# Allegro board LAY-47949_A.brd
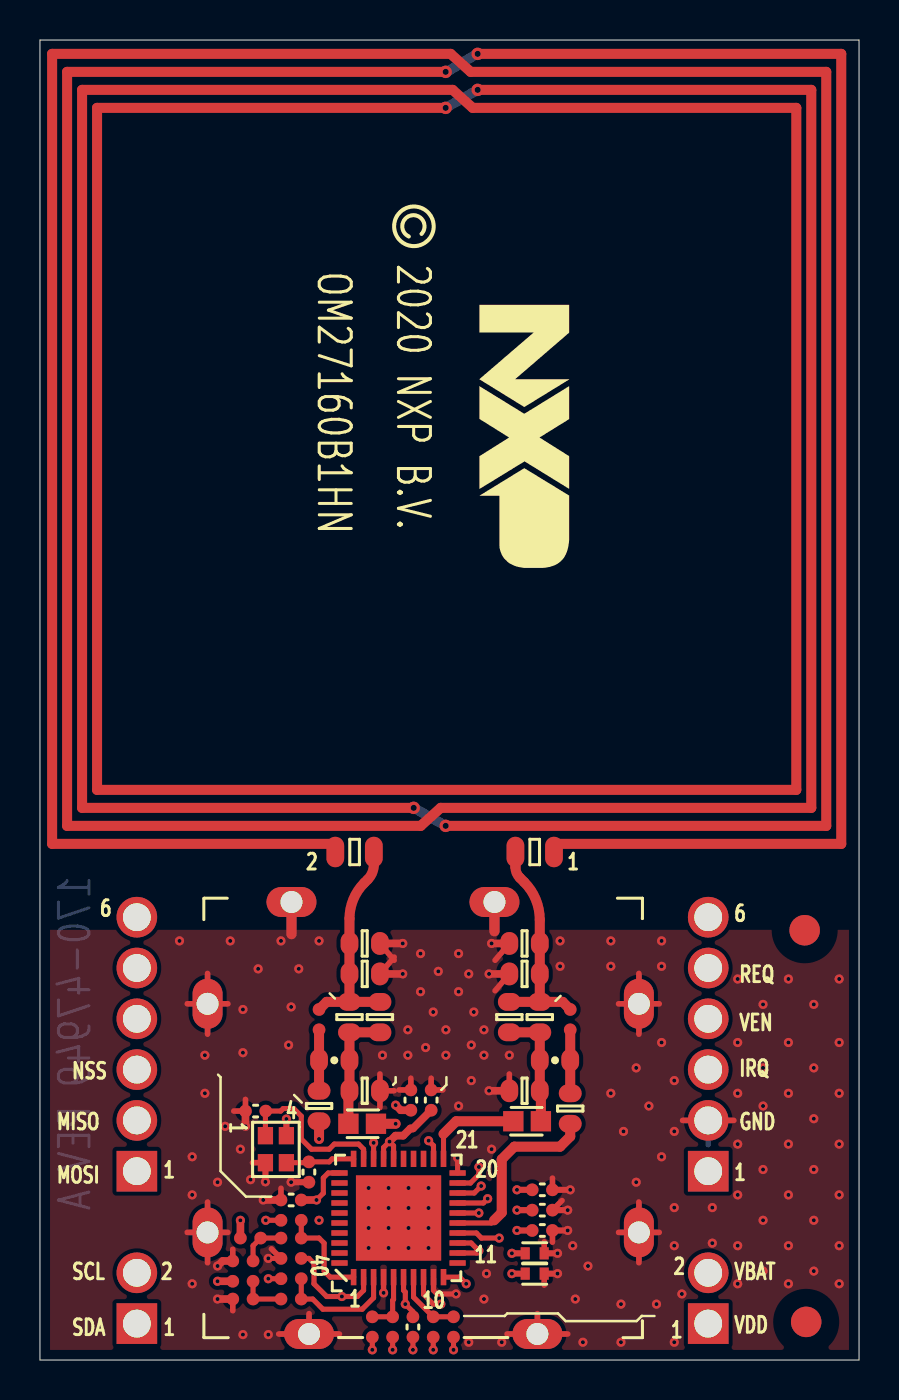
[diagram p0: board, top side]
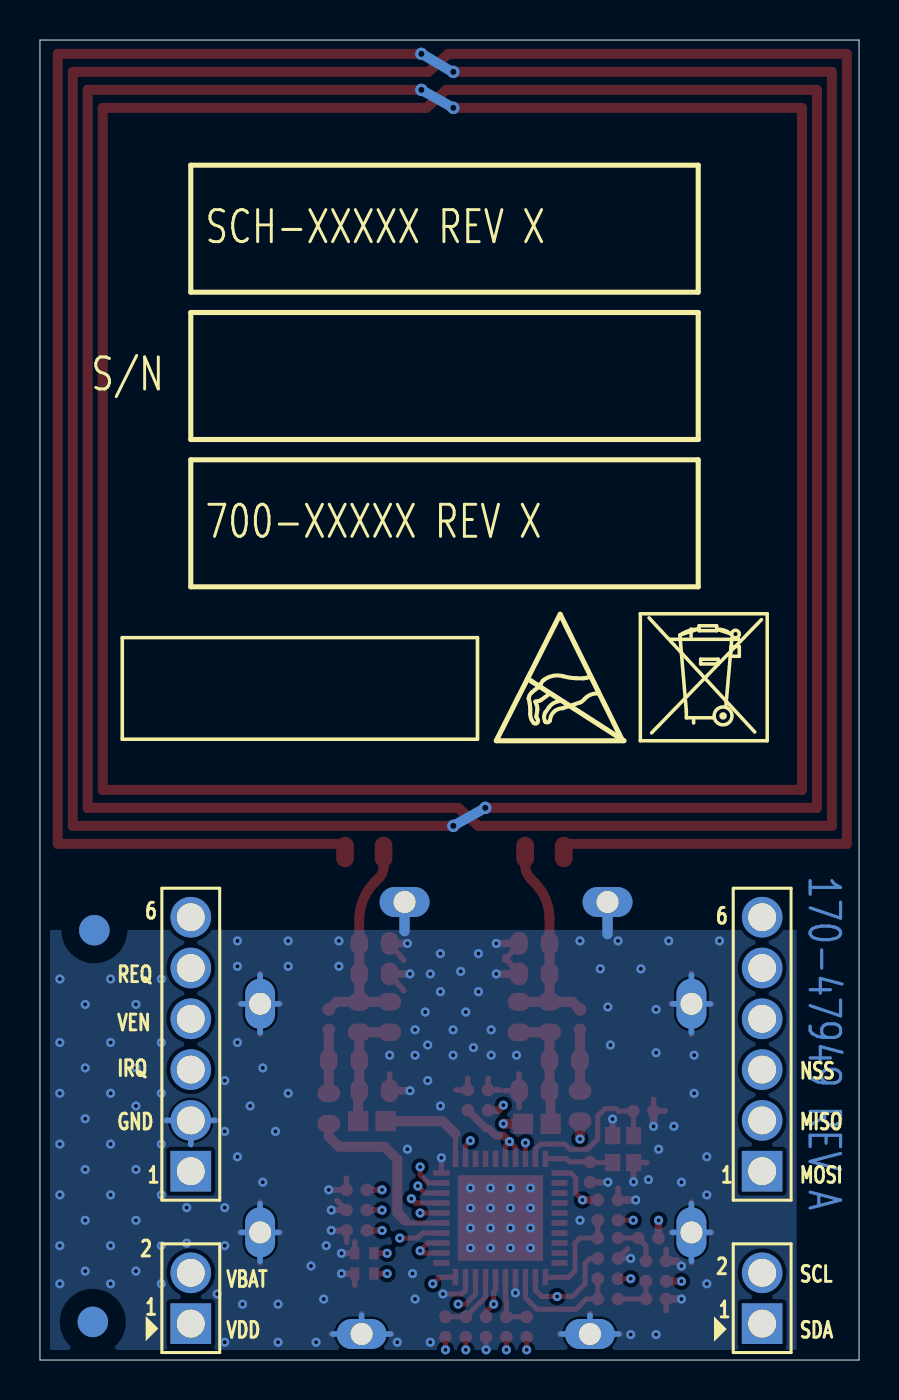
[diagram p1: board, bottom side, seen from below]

Outline 41 x 66 mm; copper layers: TOP, L2_INT_1, L3_INT_2, BOTTOM. Coordinates in mm from the lower left corner of the outline.
Outline path: 0,66 0,0 41,0 41,66 0,66

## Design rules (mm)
constraint set DEFAULT: min track width 0.127

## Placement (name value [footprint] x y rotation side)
ANT1  ANTENNA  [ANTENNA_4T_40X40]  25.76 25.81 270 top
C1  10PF  [CC0402_25]  10.79 12.45 180 top
C2  10PF  [CC0402_25]  13.46 9.4 270 top
C3  2.2UF  [CC0402_25]  25.15 7.49 180 top
C4  2.2UF  [CC0402_25]  25.15 6.48 180 top
C6  0.1uF  [CC0402_25]  25.15 8.51 0 top
C7  2.2UF  [CC0402_25]  19.58 13 270 top
C8  2.2UF  [CC0402_25]  12.57 8 0 top
C9  1uF  [CC0402_25]  18.67 1.65 270 top
C10  4.7uF  [CC0402_TOL0P15]  24.77 4.32 0 top
C11  4.7uF  [CC0402_TOL0P15]  24.77 5.33 0 top
C12  0.1uF  [CC0402_25]  18.57 13 90 top
C13  1000pF  [CC0603_OV]  26.54 12.57 90 top
C14  56 PF  [CC0603_OV]  23.49 17.14 90 top
C15  22 PF  [CC0603_OV]  25.02 17.14 90 top
C16  680PF  [CC0603_OV]  24.26 13.46 180 top
C17  120PF  [CC0603_OV]  24.26 20.83 180 top
C18  2.2PF  [CC0603_OV]  24.26 19.3 180 top
C19  680PF  [CC0603_OV]  16.26 13.46 180 top
C20  120PF  [CC0603_OV]  16.26 20.83 180 top
C21  2.2PF  [CC0603_OV]  16.26 19.3 180 top
C22  22 PF  [CC0603_OV]  15.49 17.14 90 top
C23  56 PF  [CC0603_OV]  17.02 17.14 90 top
C24  1000pF  [CC0603_OV]  13.97 12.7 90 top
J1  HDR_1X2  [SKT1X2_2P54_TH_BSE]  33.45 1.82 90 bottom
J2  HDR_1X2  [SKT1X2_2P54_TH_BSE]  4.85 1.82 90 bottom
J3  AGPS1-06-BCZ-1.3  [SKT1X6_2P54_TH_BSE]  33.45 9.44 90 bottom
J4  AGPS1-06-BCZ-1.3  [SKT1X6_2P54_TH_BSE]  4.85 9.44 90 bottom
L1  160nH  [IND_0603A]  24.38 11.94 0 top
L2  160nH  [IND_0603A]  16.13 11.81 180 top
NOREF  -  []  33.45 9.44 90 top
NOREF#2  -  []  25.34 3.99 90 top
NOREF#3  -  []  34.72 -4.53 0 top
NOREF#4  -  []  29.64 -7.07 0 top
NOREF#5  -  []  18.69 56.68 270 top
NOREF#6  -  []  24.19 3.99 0 top
NOREF#7  -  []  4.85 9.44 90 top
NOREF#8  -  []  -379.73 257.05 0 top
NOREF#9  -  []  34.72 -4.53 90 top
NOREF#10  -  []  25.34 5.01 90 top
NOREF#11  -  []  6.12 -4.53 90 top
NOREF#12  -  []  24.29 5.33 0 top
NOREF#13  -  []  -406.4 -264.03 0 top
NOREF#14  -  []  29.98 6.38 90 top
NOREF#15  -  []  -21.59 -39.88 0 top
NOREF#16  -  []  13.47 1.3 0 top
NOREF#17  -  []  33.45 1.82 90 top
NOREF#18  -  []  6.12 -4.53 0 top
NOREF#19  -  [unnamed#2]  38.28 21.49 0 top
NOREF#20  -  []  3.58 -7.07 90 top
NOREF#21  -  []  22 52.75 270 top
NOREF#22  -  []  1.04 -7.07 0 top
NOREF#23  -  []  0 66 0 top
NOREF#24  -  []  8.39 1.3 0 top
NOREF#25  -  []  32.18 -7.07 90 top
NOREF#26  -  []  19.1 31.04 0 top
NOREF#27  -  []  4.85 1.82 90 top
NOREF#28  -  [unnamed#2]  38.35 1.91 0 top
NOREF#29  -  []  24.29 4.32 0 top
NOREF#30  -  []  4.85 4.36 0 top
NOREF#31  -  []  14.86 25.81 0 top
NOREF#32  -  []  29.98 1.3 90 top
NOREF#33  -  []  33.45 9.44 90 top
NOREF#34  -  []  41 0 90 top
NOREF#35  -  []  4.85 9.44 90 top
NOREF#36  -  []  24.19 5.01 0 top
NOREF#37  -  []  175.18 226.56 0 top
NOREF#38  -  []  12.59 22.9 0 top
NOREF#39  -  []  18.14 30.96 180 bottom
NOREF#40  -  []  33.45 46.02 180 bottom
NOREF#41  -  []  36.88 31.04 180 bottom
NOREF#42  -  []  10.95 30.96 180 bottom
NOREF#43  -  [unnamed#2]  38.35 1.91 180 bottom
NOREF#44  -  []  33.45 38.66 180 bottom
NOREF#45  -  []  33.45 53.39 180 bottom
NOREF#46  -  [unnamed#2]  38.28 21.49 180 bottom
R1  0  [RC0402_25]  12.57 6.1 0 top
R2  0  [RC0402_25]  12.57 3.05 0 top
R3  0  [RC0402_25]  17.65 1.65 90 top
R4  0  [RC0402_25]  20.7 1.65 90 top
R5  0  [RC0402_25]  19.69 1.65 90 top
R6  0  [RC0402_25]  16.64 1.65 90 top
R7  0  [RC0402_25]  12.57 4.06 0 top
R8  0  [RC0402_25]  12.57 6.99 0 top
R9  100k  [RC0402_25]  12.57 5.08 180 top
R10  100k  [RC0402_25]  10.54 6.1 0 top
R11  100k  [RC0402_25]  10.16 3.94 0 top
R12  100k  [RC0402_25]  10.16 4.95 180 top
R13  100k  [RC0402_25]  10.16 3.05 180 top
R14  0  [RC0402_25]  26.54 17.02 90 top
R15  2.2K  [RC0603_OV]  25.78 14.99 180 top
R16  1.5 OHM  [RC0805_OV]  24.77 25.4 0 top
R17  1.5 OHM  [RC0805_OV]  15.75 25.4 180 top
R18  2.2K  [RC0603_OV]  14.73 14.99 180 top
R19  0  [RC0402_25]  13.97 17.02 90 top
SH1  RF-SHIELD-8  [SHIELD_PN7150_22X22]  19.19 12.1 0 top
U1  PN7160B1HN/C100  [QFN40_0P5_4P25X4P25]  17.95 7.1 90 top
Y1  27.12MHz  [XTAL4_2P1X1P7MM_SM]  11.81 10.54 270 top

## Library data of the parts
ANT1 = L104
C1-C4 C6-C24 = CAP_NP
J1 J2 = CONN_HDR_2X1
J3 J4 = CONN_HDR_6X1
L1 L2 = INDUCTOR
R1-R19 = RES
SH1 = SHIELD-RF_8P
U1 = PN7160_HVQFN40_A
Y1 = XTAL_13

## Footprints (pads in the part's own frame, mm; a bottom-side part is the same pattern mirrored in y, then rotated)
ANTENNA_4T_40X40
  rect 0.508x0.508 smd: 1(0,0)
  round 0.508 smd: 2(0,-10.9)
CC0402_25
  round 0.635 smd: 1(-0.508,0) 2(0.508,0)
CC0402_TOL0P15
  rect 0.457x0.61 smd: 1(-0.475,0) 2(0.475,0)
CC0603_OV
  oval 0.889x1.143 smd: 1(-0.762,0) 2(0.762,0)
IND_0603A
  rect 1.016x1.016 smd: 1(-0.69,0) 2(0.69,0)
QFN40_0P5_4P25X4P25
  rect 0.813x0.279 smd: 1(-2.956,2.25) 2(-2.956,1.75) 3(-2.956,1.25) 4(-2.956,0.75) 5(-2.956,0.25) 6(-2.956,-0.25) 7(-2.956,-0.75) 8(-2.956,-1.25) 9(-2.956,-1.75) 10(-2.956,-2.25) 21(2.956,-2.25) 22(2.956,-1.75) 23(2.956,-1.25) 24(2.956,-0.75) 25(2.956,-0.25) 26(2.956,0.25) 27(2.956,0.75) 28(2.956,1.25) 29(2.956,1.75) 30(2.956,2.25)
  rect 0.279x0.813 smd: 11(-2.25,-2.956) 12(-1.75,-2.956) 13(-1.25,-2.956) 14(-0.75,-2.956) 15(-0.25,-2.956) 16(0.25,-2.956) 17(0.75,-2.956) 18(1.25,-2.956) 19(1.75,-2.956) 20(2.25,-2.956) 31(2.25,2.956) 32(1.75,2.956) 33(1.25,2.956) 34(0.75,2.956) 35(0.25,2.956) 36(-0.25,2.956) 37(-0.75,2.956) 38(-1.25,2.956) 39(-1.75,2.956) 40(-2.25,2.956)
  rect 4.267x4.267 smd: 41(0,0)
RC0402_25
  round 0.635 smd: 1(-0.508,0) 2(0.508,0)
RC0603_OV
  oval 0.889x1.143 smd: 1(-0.762,0) 2(0.762,0)
RC0805_OV
  oval 0.889x1.524 smd: 1(-0.965,0) 2(0.965,0)
SHIELD_PN7150_22X22
  oval 1.5x2.5 hole 1.1: 1(-10.798,-5.718) 4(10.792,-5.718) 5(10.792,5.712) 8(-10.798,5.712)
  oval 2.5x1.5 hole 1.1: 2(-5.718,-10.798) 3(5.712,-10.798) 6(3.563,10.803) 7(-6.597,10.803)
SKT1X2_2P54_TH_BSE
  rect 2.032x2.032 hole 1.397: 1(0,0)
  round 2.032 hole 1.397: 2(2.54,0)
SKT1X6_2P54_TH_BSE
  rect 2.032x2.032 hole 1.397: 1(0,0)
  round 2.032 hole 1.397: 2(2.54,0) 3(5.08,0) 4(7.62,0) 5(10.16,0) 6(12.7,0)
unnamed#2
  round 1.524 smd: (0,0)
XTAL4_2P1X1P7MM_SM
  rect 0.864x0.762 smd: 1(-0.675,-0.525) 2(0.675,-0.525) 3(0.675,0.525) 4(-0.675,0.525)

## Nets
GND: C1.2 C2.2 C3.1 C4.1 C6.2 C7.1 C8.1 C9.2 C10.2 C11.2 C12.2 C16.2 C17.2 C18.2 C19.1 C20.1 C21.1 J3.2 R9.2 R12.2 R13.2 SH1.1 SH1.2 SH1.3 SH1.4 SH1.5 SH1.6 SH1.7 SH1.8 U1.4 U1.9 U1.20 U1.41 Y1.2 Y1.4
VBAT: C10.1 C11.1 C12.1 J1.2 U1.12 U1.13 U1.28
VDD_PAD: C9.1 J1.1 R10.1 R11.1 U1.6
DWL_REQ: J3.5 R9.1 U1.2
I2C_ADR0: R1.1 R10.2 R12.1
I2C_ADR1: R2.1 R11.2 R13.1
I2C_SCL: J2.2 R4.1
I2C_SDA: J2.1 R3.1
IRQ: J3.3 U1.8
RXN: C13.1 U1.15
RXP: C24.1 U1.16
SPI_MISO: J4.2 R6.1
SPI_MOSI: J4.1 R7.1
SPI_NSS: J4.3 R8.1
SPI_SCK: J4.4 R5.1
TX1: L1.1 U1.21
TX2: L2.1 U1.19
VEN: J3.4 U1.10
XTAL_CLK1: C2.1 U1.30 Y1.3
XTAL_CLK2: C1.1 U1.29(XTAL2) Y1.1
N17603649: R1.2 R8.2 U1.1
N17603709: R2.2 R7.2 U1.3
N17603712: R3.2 R6.2 U1.5
N17603715: R4.2 R5.2 U1.7
N17605280: C3.2 C4.2 U1.14 U1.18 U1.22
N17605634: C6.1 U1.17
N17606479: C7.2 C8.2 U1.26 U1.27 U1.31
N17608331: ANT1.1 R16.2
N17608352: ANT1.2 R17.2
N17608403: C14.2 C15.2 C17.1 C18.1 R14.2 R16.1
N17608431: C20.2 C21.2 C22.2 C23.2 R17.1 R19.2
N17608486: C14.1 C15.1 C16.1 L1.2 R15.2
N17608550: C19.2 C22.1 C23.1 L2.2 R18.1
N17608728: C24.2 R18.2 R19.1
N17608753: C13.2 R14.1 R15.1

Pads without a net: J3 1 6; J4 5 6; U1 11 23 24 25 32 33 34 35 36 37 38 39 40

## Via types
v1: diameter 0.457, hole 0.203, TOP to BOTTOM, 160 vias
v2: diameter 0.62, hole 0.31, TOP to BOTTOM, 6 vias
v3: diameter 0.457, hole 0.206, TOP to BOTTOM, 16 vias

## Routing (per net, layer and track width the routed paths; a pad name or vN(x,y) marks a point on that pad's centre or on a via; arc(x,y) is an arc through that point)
GND: length 155.8
  TOP w0.254: U1.9 19.7,3.48 19.88,3.3 v1(20.83,3.3) ; C9.2 v1(18.67,0.51) ; U1.4 v1(17.2,3.36) ; U1.20 v1(20.91,10.11) ; R9.2 v1(11.43,5.08)
  TOP w0.279: 10.29,13.03 C1.2 9.7,12.45 ; 19.58,14.09 C7.1 20.17,13.5 ; 10.64,9.87 Y1.2 ; SH1.1 8.39,7.9 ; SH1.1 9.41,6.38 ; SH1.1 7.37,6.38 ; SH1.1 8.39,4.86 ; 22.78,19.99 C17.2 ; SH1.5 29.98,19.33 ; SH1.5 31,17.81 ; SH1.5 29.98,16.29 ; SH1.5 28.96,17.81 ; 11.95,1.3 SH1.2 ; SH1.2 14.99,1.3 ; SH1.2 13.47,2.32 ; 22.78,18.46 C18.2 ; C21.1 17.73,20.14 ; C19.1 17.73,13.46 ; C19.1 17.02,12.62 ; C19.1 17.02,14.3 ; SH1.4 29.98,7.9 ; SH1.4 28.96,6.38 ; SH1.4 31,6.38 ; SH1.4 29.98,4.86 ; SH1.3 24.9,2.32 ; SH1.3 26.42,1.3 ; SH1.3 23.38,1.3 ; 8.39,16.29 SH1.8 ; SH1.8 7.37,17.81 ; SH1.8 8.39,19.33 ; SH1.8 9.41,17.81 ; C3.1 26.13,7.97 ; 25.65,5.89 C4.1 ; 11.59,5.56 R9.2 ; 32.17,11.98 J3.2 34.73,11.98 ; 9.65,2.46 R13.2 ; R12.2 9.65,5.54 ; C16.2 23.49,14.3 ; C20.1 17.73,19.99 ; C11.2 25.24,5.91 ; 25.24,3.75 C10.2 ; 18.57,14.09 C12.2 17.98,13.5 ; C8.1 12.07,8.59 ; C6.2 25.65,9.09
  TOP w0.305: C10.2 v1(25.91,4.32) ; Y1.2 v1(11.29,8.91) ; C11.2 v1(25.91,5.33) ; Y1.4 v1(12.34,12.05) ; C4.1 v1(26.42,6.48) ; C6.2 v1(26.54,8.51) ; C3.1 v1(26.42,7.49) ; C2.2 v1(12.57,8.89)
  TOP w0.381: C17.2 v1(22.61,20.83) ; R12.2 9.14,4.95 v1(8.89,4.7) ; C18.2 v1(22.48,19.3) ; C20.1 v1(18.16,20.83) ; C1.2 v1(10.29,11.68) ; C16.2 v1(22.48,13.46) ; C21.1 v1(18.16,19.3) ; C8.1 v1(11.18,8) ; R13.2 v1(8.89,3.05)
  TOP w0.508: SH1.6 22.75,21.44 ; SH1.7 12.59,21.29
  L2_INT_1 w0.279: 28.91,6.38 SH1.4 ; SH1.4 29.98,5.31 ; SH1.4 31.05,6.38 ; SH1.4 29.98,7.45 ; SH1.5 31.05,17.81 ; SH1.5 29.98,16.74 ; SH1.5 29.98,18.88 ; SH1.5 28.91,17.81 ; SH1.1 9.46,6.38 ; SH1.1 8.39,7.45 ; SH1.1 7.32,6.38 ; SH1.1 8.39,5.31 ; SH1.8 8.39,18.88 ; SH1.8 9.46,17.81 ; SH1.8 7.32,17.81 ; SH1.8 8.39,16.74 ; 14.54,1.3 SH1.2 12.4,1.3 ; 23.83,1.3 SH1.3 25.97,1.3 ; 32.17,11.98 J3.2 34.73,11.98
  L2_INT_1 w0.508: SH1.7 12.59,21.29 ; SH1.6 22.75,21.44
  L3_INT_2 w0.279: 33.45,10.77 J3.2 ; J3.2 34.66,11.98 ; J3.2 32.24,11.98 ; 28.99,17.81 SH1.5 ; SH1.5 30.97,17.81 ; SH1.5 29.98,16.82 ; SH1.5 29.98,18.8 ; SH1.4 30.97,6.38 ; SH1.4 29.98,7.37 ; SH1.4 29.98,5.39 ; SH1.8 8.39,18.8 ; SH1.8 9.38,17.81 ; SH1.8 7.4,17.81 ; SH1.8 8.39,16.82 ; 14.46,1.3 SH1.2 12.48,1.3 ; 23.91,1.3 SH1.3 25.89,1.3 ; SH1.1 9.38,6.38 ; SH1.1 7.4,6.38 ; SH1.1 8.39,7.37
  L3_INT_2 w0.508: SH1.6 22.75,21.44 ; SH1.7 12.59,21.29
  BOTTOM w0.279: J3.2 34.66,11.98 ; J3.2 32.24,11.98 ; J3.2 33.45,10.77 ; SH1.4 29.98,7.82 ; SH1.4 29.04,6.38 ; SH1.4 29.98,4.94 ; SH1.4 30.92,6.38 ; 12.03,1.3 SH1.2 ; SH1.2 13.47,2.24 ; SH1.2 14.91,1.3 ; 29.04,17.81 SH1.5 ; SH1.5 29.98,16.37 ; SH1.5 29.98,19.25 ; SH1.5 30.92,17.81 ; 23.46,1.3 SH1.3 ; SH1.3 24.9,2.24 ; SH1.3 26.34,1.3 ; SH1.1 8.39,7.82 ; SH1.1 8.39,4.94 ; SH1.1 9.33,6.38 ; SH1.1 7.45,6.38 ; SH1.8 8.39,19.25 ; SH1.8 8.39,16.37 ; SH1.8 9.33,17.81 ; SH1.8 7.45,17.81
  BOTTOM w0.508: SH1.7 12.59,21.29 ; SH1.6 22.75,21.44
  vias: v1(6.98,20.95) v1(7.62,10.16) v1(7.62,8.26) v1(7.62,3.81) v1(8.25,15.24) v1(8.25,13.34) v1(8.89,8.89) v1(9.27,11.68) v1(9.53,20.95) v1(10.03,10.54) v1(10.16,17.53) v1(10.16,15.37) v1(10.16,1.27) v1(10.54,9.02) v1(10.92,19.56) v1(11.43,1.27) v1(12.07,20.95) v1(12.45,15.75) v1(12.57,17.65) v1(12.95,19.56) v1(13.97,20.95) v1(13.97,6.99) v1(17.14,15.24) v1(18.41,16.51) v1(18.41,15.24) v1(19.05,20.32) v1(19.05,18.41) v1(19.3,15.62) v1(19.69,17.4) v1(19.94,19.43) v1(20.32,16.51) v1(20.32,15.24) v1(20.95,20.32) v1(20.95,18.41) v1(20.95,12.7) v1(21.46,19.3) v1(21.46,0.89) v1(21.59,15.75) v1(21.59,13.97) v1(21.72,17.4) v1(22.23,16.51) v1(22.23,15.24) v1(22.23,3.05) v1(22.35,4.32) v1(22.61,10.54) v1(23.11,0.89) v1(23.49,15.24) v1(26.03,20.95) v1(26.03,19.68) v1(26.67,5.71) v1(26.8,3.05) v1(27.18,0.89) v1(27.43,4.7) v1(28.58,20.95) v1(28.58,19.68) v1(28.58,13.34) v1(29.08,2.79) v1(29.08,0.89) v1(29.21,11.43) v1(29.84,14.61) v1(29.84,8.89) v1(30.48,12.7) v1(30.86,2.79) v1(31.12,20.95) v1(31.12,19.68) v1(31.12,15.88) v1(31.12,10.16) v1(31.75,13.97) v1(31.75,11.43) v1(31.75,7.62) v1(31.75,5.71) v1(31.75,0.89) v1(32.13,3.3) v1(33.66,7.62) v1(33.66,5.84) v1(34.92,19.05) v1(34.92,15.88) v1(34.92,13.34) v1(34.92,10.79) v1(34.92,8.26) v1(34.92,5.71) v1(34.92,3.81) v1(36.2,17.78) v1(36.2,14.61) v1(36.2,12.7) v1(36.2,9.53) v1(36.2,6.99) v1(36.2,4.45) v1(37.47,19.05) v1(37.47,15.88) v1(37.47,13.34) v1(37.47,10.79) v1(37.47,8.26) v1(37.47,5.71) v1(37.47,3.81) v1(38.73,17.78) v1(38.73,14.61) v1(38.73,12.07) v1(38.73,9.53) v1(38.73,6.99) v1(38.73,4.45) v1(40.01,19.05) v1(40.01,15.88) v1(40.01,13.34) v1(40.01,10.79) v1(40.01,8.26) v1(40.01,5.71) v1(40.01,3.81) v3(16.45,8.6) v3(16.45,7.6) v3(16.45,6.6) v3(16.45,5.6) v3(17.45,8.6) v3(17.45,7.6) v3(17.45,6.6) v3(17.45,5.6) v3(18.45,8.6) v3(18.45,7.6) v3(18.45,6.6) v3(18.45,5.6) v3(19.45,8.6) v3(19.45,7.6) v3(19.45,6.6) v3(19.45,5.6)
VBAT: length 30.5
  TOP w0.254: U1.12 21.86,5.35 v1(21.97,5.46) 21.58,5.85 U1.13 ; U1.28 v1(16.7,10.86)
  TOP w0.305: C11.1 v1(23.62,5.33) ; C10.1 v1(23.62,4.32)
  TOP w0.381: v1(17.8,12.74) 18.06,12.49 C12.1
  L2_INT_1 w0.381: v1(16.7,10.86) 16.7,12.02 17.42,12.74 v1(17.8,12.74) 18.35,12.2 18.35,11.58 18.07,11.3 18.07,10.76 20.6,8.23 20.6,6.29 21.42,5.46 v1(21.97,5.46) 22.52,5.46 22.64,5.33 v1(23.62,5.33) v1(23.62,4.32) 24.22,3.72 29.84,3.72 30.48,4.36 32.12,4.36 J1.2
VDD_PAD: length 33.9
  TOP w0.254: C9.1 18.67,2.41 v1(18.29,2.79) 18.29,3.4 18.2,3.48 U1.6
  TOP w0.381: R10.1 v1(10.03,6.99) ; R11.1 v1(8.89,3.94)
  L2_INT_1 w0.381: J1.1 26.63,1.82 26.03,2.42 23.63,2.42 22.86,1.65 19.43,1.65 v1(18.29,2.79) 16.64,2.79 12.99,6.44 11.08,6.44 10.54,6.97 10.54,6.99 v1(10.03,6.99) 10.03,4.53 9.44,3.94 v1(8.89,3.94)
DWL_REQ: length 35.2
  TOP w0.254: U1.2 16.2,3.48 15.89,3.18 v1(15.11,3.18) 14.35,3.18 13.72,3.81 13.72,4.83 13.46,5.08 R9.1
  L3_INT_2 w0.254: J3.5 31.75,17.9 31.75,17.65 27.2,13.11 27.2,5.23 26.8,4.83 21.34,4.83 20.45,3.94 15.88,3.94 v1(15.11,3.18)
I2C_ADR0: length 2.3
  TOP w0.254: R1.1 R10.2 10.67,5.71 R12.1
I2C_ADR1: length 2.3
  TOP w0.254: R2.1 R13.1 R11.2
I2C_SCL: length 18.6
  TOP w0.254: R4.1 v1(20.7,0.51)
  L3_INT_2 w0.254: J2.2 6.8,2.41 9.14,2.41 9.78,3.05 14.35,3.05 14.99,2.41 16.76,2.41 17.36,1.82 19.39,1.82 v1(20.7,0.51)
I2C_SDA: length 14.6
  TOP w0.254: R3.1 v1(17.65,0.51)
  L3_INT_2 w0.254: J2.1 6.12,1.82 6.29,1.65 9.4,1.65 10.16,2.41 14.22,2.41 14.73,1.91 16.26,1.91 v1(17.65,0.51)
IRQ: length 24
  TOP w0.254: U1.8 19.2,3.28 19.69,2.79 v1(20.07,2.79)
  L3_INT_2 w0.254: J3.3 28.85,9.92 28.85,3.96 27.3,2.41 20.45,2.41 v1(20.07,2.79)
RXN: length 9.6
  TOP w0.254: 22.73,6.99 22.6,6.85 U1.15
  TOP w0.5: C13.1 26.54,11.18 26.03,10.67 23.75,10.67 23.11,10.03 23.11,7.37 22.73,6.99
RXP: length 11.8
  TOP w0.254: U1.16 v1(21.97,7.35)
  TOP w0.5: C24.1 v1(13.97,11.05)
  L3_INT_2 w0.5: v1(13.97,11.05) 14.99,11.05 16.13,9.91 20.01,9.91 21.54,8.37 21.54,7.78 v1(21.97,7.35)
SPI_MISO: length 22.5
  TOP w0.254: R6.1 v1(16.64,0.51)
  L2_INT_1 w0.254: v1(16.64,0.51) 16,0.51 13.97,2.54 10.41,2.54 9.65,1.78 6.98,1.78 6.22,2.54 6.22,10.61 J4.2
SPI_MOSI: length 10.4
  TOP w0.254: R7.1 v1(11.43,4.06)
  L3_INT_2 w0.254: v1(11.43,4.06) 10.17,5.33 7.37,5.33 6.29,6.41 6.29,8 J4.1
SPI_NSS: length 11
  TOP w0.254: R8.1 v1(11.3,6.99)
  L3_INT_2 w0.254: v1(11.3,6.99) 9.65,8.64 9.65,9.72 5.75,13.62 J4.3
SPI_SCK: length 30.3
  TOP w0.254: R5.1 v1(19.69,0.51)
  L2_INT_1 w0.254: J4.4 5.75,16.16 6.73,15.18 6.73,3.05 7.37,2.41 9.4,2.41 10.41,3.43 14.1,3.43 15.62,1.91 18.29,1.91 v1(19.69,0.51)
TX1: length 5
  TOP w0.254: 20.2,11.3 U1.21
  TOP w0.5: L1.1 20.83,11.94 20.2,11.3
TX2: length 8.2
  TOP w0.254: U1.19 21.55,8.85 21.97,9.27 v1(21.97,9.65)
  TOP w0.5: L2.1 v1(17.8,11.81)
  L3_INT_2 w0.5: v1(17.8,11.81) 20.7,11.81 21.97,10.54 v1(21.97,9.65)
VEN: length 23
  TOP w0.254: U1.10 21,4.14 v1(21.34,3.81)
  L3_INT_2 w0.254: J3.4 28.07,11.68 28.07,4.57 27.3,3.81 v1(21.34,3.81)
XTAL_CLK1: length 3.4
  TOP w0.254: Y1.3 13.42,9.87 C2.1 14.48,9.91 14.63,10.06 U1.30
XTAL_CLK2: length 8.4
  TOP w0.254: Y1.1 11.29,12.43 C1.1 12.05,12.45 12.18,12.57 12.7,12.57 13.08,12.19 13.08,11.05 13.59,10.54 14.48,10.54 14.73,10.79 15.95,10.79 16.2,10.54 U1.29
N17603649: length 5.1
  TOP w0.254: R8.2 R1.2 13.97,6.1 14.22,5.84 14.22,4.45 14.52,4.14 U1.1
N17603709: length 6.1
  TOP w0.254: U1.3 16.7,3.11 16.13,2.54 14.16,2.54 13.65,3.05 R2.2 R7.2
N17603712: length 3
  TOP w0.254: U1.5 17.7,3.03 17.65,2.98 R3.2 R6.2
N17603715: length 3.4
  TOP w0.254: R4.2 R5.2 18.7,3.14 U1.7
N17605280: length 16.3
  TOP w0.254: v1(22.09,8.7) 21.74,8.35 U1.18 ; v1(19.46,10.96) 19.46,10.96 19.7,10.72 U1.22 ; v1(22.99,6.1) 22.1,6.1 21.84,6.35 U1.14
  TOP w0.305: C4.2 v1(23.88,6.48) ; C3.2 v1(23.88,7.49)
  L2_INT_1 w0.381: v1(23.88,7.49) v1(23.88,6.48) 23.37,6.48 v1(22.99,6.1) 22.29,6.1 21.42,6.96 21.42,8.04 v1(22.09,8.7) 21.34,9.45 21.34,9.77 21.45,9.88 21.45,10.41 20.9,10.96 v1(19.46,10.96)
N17605634: length 4
  TOP w0.254: U1.17 22.19,7.85 v1(22.41,8.07)
  TOP w0.305: C6.1 v1(23.88,8.51)
  L2_INT_1 w0.381: v1(22.41,8.07) 23.43,8.07 v1(23.88,8.51)
N17606479: length 17.1
  TOP w0.254: U1.27 17.2,10.62 v1(17.49,10.92) 17.7,10.71 U1.26 ; U1.31 14.43,9.35 14.18,9.1 14.18,8.34 v1(13.84,8)
  TOP w0.381: C7.2 18.67,11.58 18.54,11.58 18.18,11.22 17.79,11.22 v1(17.49,10.92) ; C8.2 v1(13.84,8)
  L3_INT_2 w0.381: v1(13.84,8) 13.84,9.08 12.72,10.2 12.72,11.35 13.61,12.23 16.18,12.23 v1(17.49,10.92)
N17608331: length 222.6
  TOP w0.5: v2(21.91,65.31) 40.11,65.31 40.11,25.81 ANT1.1 ; v2(20.31,64.41) 1.36,64.41 1.36,26.71 19.06,26.71 20.06,27.61 38.61,27.61 38.61,63.51 v2(21.91,63.51)
  BOTTOM w0.5: v2(21.91,65.31) 21.88,65.31 20.36,64.41 v2(20.31,64.41) ; v2(21.91,63.51) 20.31,62.61
N17608352: length 360.7
  TOP w0.5: v2(20.31,62.61) 2.86,62.61 2.86,28.51 37.86,28.51 37.86,62.61 21.66,62.61 20.66,63.51 2.11,63.51 2.11,27.61 v2(18.71,27.61) ; v2(20.31,26.71) 39.36,26.71 39.36,64.41 21.56,64.41 20.56,65.31 0.61,65.31 0.61,25.81 ANT1.2
  BOTTOM w0.5: v2(20.31,26.71) v2(18.71,27.61)
N17608403: length 11.1
  TOP w0.5: R16.1 23.8,24.64 arc(23.86,24.36) 24.02,24.12 24.24,23.89 arc(24.82,23.03) 25.02,22.01 C17.1 C18.1 C15.2 ; C15.2 26.16,17.91 R14.2 ; C15.2 C14.2
N17608431: length 11
  TOP w0.5: R17.1 16.71,24.77 arc(16.63,24.37) 16.41,24.03 16.23,23.85 arc(15.69,23.03) 15.49,22.07 C20.2 C21.2 C22.2 ; R19.2 14.35,17.91 C22.2 ; C22.2 C23.2
N17608486: length 6
  TOP w0.5: L1.2 25.07,13.41 C16.1 R15.2 C15.1 C14.1
N17608550: length 6.1
  TOP w0.5: C23.1 C22.1 R18.1 C19.2 15.44,13.41 L2.2
N17608728: length 3
  TOP w0.5: C24.2 R18.2 R19.1
N17608753: length 3.2
  TOP w0.5: R14.1 R15.1 C13.2

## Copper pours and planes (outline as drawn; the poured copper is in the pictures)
GND on TOP: 40.5,21.51 40.5,0.5 0.5,0.5 0.5,21.51 ; 6 cut-outs
GND on BOTTOM: 40.5,21.51 40.5,0.5 0.5,0.5 0.5,21.51
GND on L2_INT_1: 40.5,21.51 40.5,0.5 0.5,0.5 0.5,21.51 ; 6 cut-outs
GND on L3_INT_2: 40.5,21.51 40.5,0.5 0.5,0.5 0.5,21.51 ; 4 cut-outs

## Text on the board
BOTTOM: 07 | L4_SS | 170-47949 REV A
Board Geometry/Soldermask Bottom: 08 | SECONDARY SOLDERMASK
Ref Des/Silkscreen Bottom: NSS | MISO | MOSI | SCL | SDA | VBAT | VDD | REQ | VEN | IRQ | GND | 09 | SECONDARY SILKSCREEN
User.Comments: 1 OF 1 | TEST PROBE | 1/1 | 1 | 2
TOP: 04 | L1_PS
Board Geometry/Soldermask Top: 03 | PRIMARY SOLDERMASK
Ref Des/Silkscreen Top: MISO | MOSI | NSS | SCL | SDA | VBAT | VDD | REQ | VEN | IRQ | GND | 02 | PRIMARY SILKSCREEN | OM27160B1HN
L2_INT_1: 05 | L2_INT_1
L3_INT_2: 06 | L3_INT_2
XSECTION_CHART: *  SURFACE - AIR 0 MIL | *  DIELECTRIC - DRY_FILM_MASK 0.8 MIL | L1 TOP CONDUCTOR - 1OZ_COPPER 1.4 MIL | *  DIELECTRIC - FR-4 18.4 MIL | L2 L2_INT_1 CONDUCTOR - 1/2OZ_COPPER 0.63 MIL | *  DIELECTRIC - FR-4 20 MIL | L3 L3_INT_2 CONDUCTOR - 1/2OZ_COPPER 0.63 MIL | L4 BOTTOM PLANE - 1OZ_COPPER 1.4 MIL | DESIGN CROSS SECTION CHART | ___________________________ | TOTAL THICKNESS 62.46 MIL | 1-4
DIMENSION: SCALE: NONE | BOARD THICKNESS TOLERANCE +/-10% | 11. ELECTRICAL TEST - 100% IPCD356. PCB FABRICATOR TO PERFORM A NET COMPARE AGAINST THE IPCD356 NETLIST PROVIDED BY NXP. | 8 | 22 | 19 | 16 | DETAIL | LAYER STACKUP | PRIMARY DATUM | GRID ORIGIN | A
DISPLAY_TOP: 01 | PRIMARY PASTEMASK
User.5: 10 | SECONDARY PASTEMASK
User.14: OF 10
User.17: 22. THIS FAB_VIAFILL.ART SHOWS LOCATIONS OF VIA-IN-PAD TO BE FILLED. | 1/1 | 2
User.18: 24. | 1/1 | 3 | CAD DESIGNER: DELETE THIS FAB PAGE IF BACKDRILL IS NOT USED ON THIS DESIGN. | FAB SUPPLIER: DISREGARD THIS PAGE IF BACKDRILL REQUIRMENT IS NOT PROVIDED.
User.23: TOP TO LAYER X | BACK DRILL REFERENCE | BOTTOM TO LAYER X | LAYER X | MUST CUT LAYER | LAYER X+1 | MUST NOT CUT LAYER | LAYER X-1
User.24: FIGURE | FINISHED_SIZE | 8.0 | 8.1 | 12.2 | 43.31 | 55.0 | DRILL CHART: TOP to BOTTOM | ALL UNITS ARE IN MILS | TOLERANCE_DRILL | +0.0/-8.0 | +0.0/-8.1 | +0.0/-0.0 | +3.0/-3.0 | PLATED | QTY | 160 | 16 | 6 | 8 | 206 | TOTAL HOLES:
